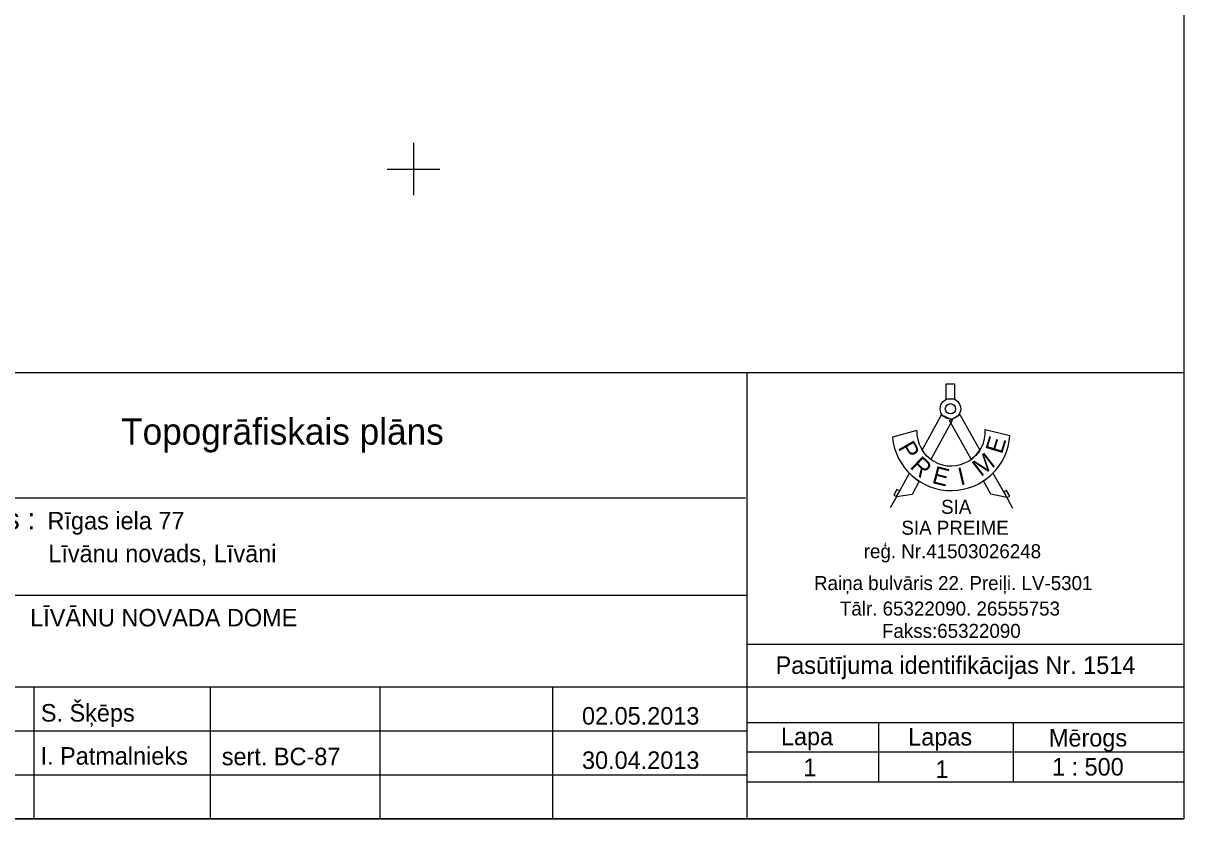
# Model space of a CAD drawing. Extents: x 634272 to 634544, y 247463 to 247653.
# Drawn here: x 634477.7 to 634543.9, y 247462.9 to 247508.3 of the extents above; entities that cross this region are included whole.
import ezdxf

# ---------------------------------------------------------------- set-up
doc = ezdxf.new("R2010")
doc.units = 0
doc.layers.add('GEOD_ELEM_####_####_#', color=7, linetype='Continuous')
doc.layers.add('RAMI_PLAN_####_TKST_#', color=7, linetype='Continuous')

msp = doc.modelspace()

# ---------------------------------------------------------------- linework, layer by layer
at = {"layer": 'GEOD_ELEM_####_####_#'}
for p, q in [((634500, 247501.5), (634500, 247500)), ((634498.5, 247500), (634500, 247500)), ((634500, 247500), (634500, 247498.5)), ((634500, 247500), (634501.5, 247500))]:
    msp.add_line(p, q, dxfattribs=at)
at = {"layer": 'RAMI_PLAN_####_TKST_#'}
for p, q in [((634469.278, 247488.398), (634543.915, 247488.398)), ((634518.996, 247488.398), (634518.996, 247462.947)), ((634543.915, 247488.398), (634543.915, 247462.947)), ((634528.694, 247485.097), (634527.3, 247484.701)), ((634528.694, 247485.097), (634527.3, 247484.701)), ((634532.593, 247485.149), (634533.998, 247484.808)), ((634532.593, 247485.149), (634533.998, 247484.808)), ((634469.278, 247481.257), (634518.916, 247481.257)), ((634527.534, 247481.314), (634527.175, 247480.675)), ((634527.534, 247481.314), (634527.175, 247480.675)), ((634533.826, 247481.263), (634534.156, 247480.665)), ((634533.826, 247481.263), (634534.156, 247480.665)), ((634469.278, 247475.707), (634518.996, 247475.707)), ((634518.996, 247472.908), (634543.915, 247472.908)), ((634478.35, 247470.48), (634478.35, 247462.947)), ((634488.394, 247470.48), (634488.394, 247462.947)), ((634498.079, 247470.48), (634498.079, 247462.947)), ((634507.919, 247470.48), (634507.919, 247462.947)), ((634518.996, 247470.48), (634543.915, 247470.48)), ((634518.996, 247468.436), (634543.915, 247468.436)), ((634518.996, 247466.766), (634543.915, 247466.766))]:
    msp.add_line(p, q, dxfattribs=at)
for points in [[(634272.074, 247653.005), (634543.915, 247653.005), (634543.915, 247462.947), (634272.074, 247462.947)], [(634530.367, 247487.75), (634530.834, 247487.75), (634530.834, 247486.88), (634530.367, 247486.88)], [(634530.367, 247487.75), (634530.834, 247487.75), (634530.834, 247486.88), (634530.367, 247486.88)], [(634530.105, 247485.987), (634530.725, 247485.698), (634529.5, 247483.439), (634529.269, 247483.631), (634529.109, 247483.818), (634528.998, 247483.974)], [(634530.105, 247485.987), (634530.725, 247485.698), (634529.5, 247483.439), (634529.269, 247483.631), (634529.109, 247483.818), (634528.998, 247483.974)], [(634530.553, 247485.666), (634531.143, 247486.008), (634532.293, 247483.974), (634532.203, 247483.844), (634532.052, 247483.668), (634531.801, 247483.448)], [(634530.553, 247485.666), (634531.143, 247486.008), (634532.293, 247483.974), (634532.203, 247483.844), (634532.052, 247483.668), (634531.801, 247483.448)], [(634528.827, 247482.195), (634528.419, 247481.443), (634527.534, 247481.314), (634528.267, 247482.647), (634528.452, 247482.478), (634528.622, 247482.338)], [(634528.827, 247482.195), (634528.419, 247481.443), (634527.534, 247481.314), (634528.267, 247482.647), (634528.452, 247482.478), (634528.622, 247482.338)], [(634533.036, 247482.659), (634533.826, 247481.263), (634532.916, 247481.466), (634532.494, 247482.215), (634532.76, 247482.412), (634532.904, 247482.535)], [(634533.036, 247482.659), (634533.826, 247481.263), (634532.916, 247481.466), (634532.494, 247482.215), (634532.76, 247482.412), (634532.904, 247482.535)], [(634527.534, 247481.317), (634527.715, 247481.64), (634527.554, 247481.729), (634527.374, 247481.405)], [(634527.534, 247481.317), (634527.715, 247481.64), (634527.554, 247481.729), (634527.374, 247481.405)], [(634533.987, 247481.349), (634533.81, 247481.674), (634533.65, 247481.588), (634533.826, 247481.262)], [(634533.987, 247481.349), (634533.81, 247481.674), (634533.65, 247481.588), (634533.826, 247481.262)]]:
    msp.add_lwpolyline(points, close=True, dxfattribs=at)
for points in [[(634469.278, 247470.48), (634518.996, 247470.48)], [(634526.529, 247465.057), (634526.529, 247468.416)], [(634534.203, 247465.057), (634534.203, 247468.416)], [(634469.278, 247467.969), (634518.996, 247467.969)], [(634469.278, 247465.458), (634518.996, 247465.458)], [(634518.996, 247465.057), (634543.915, 247465.057)], [(634469.278, 247462.947), (634543.915, 247462.947)]]:
    msp.add_lwpolyline(points, dxfattribs=at)
for radius in [0.586, 0.586, 0.293, 0.293]:
    msp.add_circle((634530.61, 247486.327), radius, dxfattribs=at)
for centre, radius, start, end in [((634530.647, 247485.022), 3.36, 185.45225, 356.36955), ((634530.647, 247485.022), 3.36, 185.45225, 356.36955), ((634530.646, 247485.022), 1.953, 177.76883, 3.78683), ((634530.646, 247485.022), 1.953, 177.76883, 3.78683)]:
    msp.add_arc(centre, radius, start, end, dxfattribs=at)

# ---------------------------------------------------------------- texts
for s, height, rotation, p in [('Topogrāfiskais plāns', 1.5, 360, (634483.323, 247484.282)), ('E', 1, 72.90018, (634533.541, 247483.7)), ('P', 1, 299.66782, (634527.594, 247484.117)), ('R', 1, 316.49601, (634528.255, 247482.982)), ('M', 1, 37.61178, (634532.352, 247482.421)), ('E', 1, 345.66821, (634529.516, 247482.108)), ('I', 1, 13.09439, (634531.172, 247481.946)), ('Pasūtījums :', 1.2, 360, (634469.602, 247479.456)), ('SIA', 0.8, 360, (634530.077, 247480.336)), ('Rīgas iela 77', 1, 360, (634479.128, 247479.446)), ('SIA PREIME', 0.8, 360, (634527.813, 247479.145)), ('reģ. Nr.41503026248', 0.8, 360, (634525.666, 247477.804)), ('Līvānu novads, Līvāni', 1, 360, (634479.171, 247477.574)), ('Raiņa bulvāris 22. Preiļi. LV-5301', 0.8, 360, (634522.83, 247475.99)), ('Tālr. 65322090. 26555753', 0.8, 360, (634524.305, 247474.535)), ('LĪVĀNU NOVADA DOME', 1, 360, (634478.139, 247473.917)), ('Fakss:65322090', 0.8, 360, (634526.706, 247473.262)), ('Pasūtījuma identifikācijas Nr. 1514', 1, 360, (634520.64, 247471.207)), ('S. Šķēps', 1, 360, (634478.746, 247468.489)), ('02.05.2013', 1, 360, (634509.602, 247468.317)), ('Lapa', 1, 360, (634520.947, 247467.144)), ('Lapas', 1, 360, (634528.203, 247467.124)), ('Mērogs', 1, 360, (634536.224, 247467.067)), ('I. Patmalnieks', 1, 360, (634478.727, 247466.032)), ('sert. BC-87', 1, 360, (634489.062, 247465.999)), ('30.04.2013', 1, 360, (634509.602, 247465.79)), ('1', 1, 360, (634522.219, 247465.375)), ('1', 1, 360, (634529.752, 247465.273)), ('1 : 500', 1, 360, (634536.4, 247465.412))]:
    msp.add_text(s, height=height, rotation=rotation, dxfattribs=at).set_placement(p)

doc.saveas('drawing.dxf')
